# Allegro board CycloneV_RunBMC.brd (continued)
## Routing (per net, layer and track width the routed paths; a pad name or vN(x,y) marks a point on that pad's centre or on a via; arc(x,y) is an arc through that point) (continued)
P0V75_AUX: length 11.7
  BOTTOM w0.254: RB17.2 34,49.13 v1(33.85,49.28) ; v1(46.3,39.63) 46.3,40.39 R8F1.2 ; EU8F1.3 48.19,42.34 ; 48.19,42.34 48.14,42.28 47.89,42.28 C8F2.1 ; 48.19,42.34 v1(48.23,42.37) ; 45.33,44.12 45.31,44.1 v1(44.87,44.1) ; 45.33,44.12 v1(45.36,44.15) 45.35,44.16 RB32.2 RB30.2 45.35,45.27 45.62,45.55 45.62,46.27 CB3.1 ; 45.33,44.12 45.33,43.91 45.32,43.9 RB37.2 RB39.2 45.32,42.42 RB40.2 RB41.2 45.32,41.84 RB42.2 C1A6.1 ; RB16.2 34.51,49.05 34.49,49.08 34.49,49.26 v1(34.46,49.28) ; RB15.2 v1(35.02,49.28) ; 33.84,48.57 33.33,48.57 RB19.2
  vias: v1(35.81,49.28) v1(36.54,49.28) v1(37.28,49.28) v1(38.09,49.28) v1(38.86,49.28) v1(39.59,49.28) v1(40.38,49.28) v1(41.12,49.28) v1(41.93,49.28) v1(42.67,49.28) v1(43.43,49.28)
P0V75_AUX_REFOUT: length 11.2
  TOP w0.254: v1(27.97,43.22) 27.97,43.21 U3.M8 ; U3.H1 v1(33.57,39.2) ; U4.M8 v1(37.75,43.16) ; U4.H1 v1(43.35,39.16) ; U2.M8 v1(18.13,43.23) ; UT7.H28 v1(24.38,30.41) ; U2.H1 v1(23.73,39.23) ; UT7.T27 v1(30.78,29.61)
  BOTTOM w0.254: CB32.1 43.47,39.29 v1(43.35,39.16) ; CB19.1 18.12,43.23 v1(18.13,43.23) ; v1(37.75,43.16) 37.74,43.17 CB21.1 ; v1(23.73,39.23) 23.4,39.56 CB24.1 ; CB66.1 24.07,30.1 v1(24.38,30.41) ; v1(33.57,39.2) 33.24,39.54 CB26.1 ; EU8F1.6 47.19,45.83 46.76,46.26 46.58,46.26 46.45,46.39 ; CB20.1 27.97,43.21 v1(27.97,43.22) ; 46.45,46.39 C8F6.1 ; 46.45,46.39 v1(46.45,46.28) ; v1(30.78,29.61) 30.88,29.61 31.25,29.98 CB68.1
P1V1_AUX: length 45
  TOP w0.254: UT7.M12 v1(27.58,16.81) UT7.N12 ; UT7.P11 v1(28.38,16.01) ; v1(26.01,22.42) 26.02,22.41 26.02,22.39 26.38,22.03 UT7.L18 ; UT7.M13 v1(26.78,17.61) ; UT7.P13 v1(28.38,17.61) ; UT7.R12 v1(29.98,16.81) ; UT7.L11 v1(25.98,16.01) ; v2(12.57,17.3) 12.57,17.87 RT66.2 ; UT7.L12 v1(25.98,16.81) ; UT7.P14 v1(28.38,18.41) ; UT7.R9 v1(29.98,14.41) ; UT7.N16 v1(27.58,20.81) ; UT7.T9 v1(30.78,14.41) ; UT7.P15 v1(28.38,20.01) ; UT7.M15 v1(26.78,20.01) ; UT7.P17 28.76,21.21 28.39,21.58 v1(28.38,21.58) ; UT7.U26 31.56,28.79 v1(31.56,28.81) ; UT7.L16 v1(25.98,20.81) UT7.K17 ; UT7.R10 v1(29.98,15.21) ; UT7.L14 v1(25.98,18.41) ; UT7.N14 v1(27.58,18.41) ; UT7.P19 v1(28.38,23.21) ; UT7.M17 27.16,21.21 26.79,21.58 v1(26.78,21.58) ; UT7.M19 27.04,22.67 27.04,22.5 26.85,22.5 v1(26.78,22.43) 26.91,22.43 26.99,22.35 27.04,22.35 27.04,22.15 UT7.M18 ; v1(27.58,22.43) 27.98,22.03 UT7.N18 ; UT7.R14 v1(29.98,18.41) ; UT7.N10 v1(27.58,15.21) UT7.N9 ; UT7.J11 v1(24.38,16.01) ; UT7.K13 v1(25.18,17.61) ; UT7.N11 v1(27.58,16.01) ; UT7.U21 v1(30.75,24.84) ; UT7.T15 v1(30.78,20.01) ; UT7.K15 v1(25.18,20.01) ; UT7.M9 v1(26.78,14.41)
  BOTTOM w0.254: v1(30.75,24.84) 31.21,25.3 CB93.1 ; v1(24.38,16.01) 24.62,15.77 CB168.1 ; v1(29.98,15.21) 29.65,14.88 CB174.1 ; v1(26.01,22.42) 26.02,22.43 26.09,22.43 CB114.1 ; CB153.1 26.98,19.21 26.96,19.23 26.96,19.83 v1(26.78,20.01) ; CB180.1 v1(26.78,14.41) ; v1(30.78,20.01) 30.59,19.82 CB148.1 ; v1(28.38,23.21) 28.43,23.26 CB111.1 ; v1(28.38,21.58) 28.39,21.59 28.62,21.59 CB128.1 ; CB165.1 29.85,16.68 v1(29.98,16.81) ; v1(27.58,18.41) 27.65,18.48 CB151.1 ; v1(28.38,17.61) 28.54,17.44 CB159.1 ; CB113.1 27.02,22.85 27.02,22.67 v1(26.78,22.43) ; CB167.1 25.74,15.77 v1(25.98,16.01) ; CB178.1 29.71,14.14 v1(29.98,14.41) ; CB130.1 25.43,21.35 v1(25.98,20.81) ; v1(29.98,18.41) 29.77,18.2 CB157.1 ; v1(27.58,15.21) 27.39,15.02 CB175.1 ; CB152.1 16.73,18.03 16.99,17.77 16.99,17.64 17,17.63 17,17.55 v1(17.04,17.58) ; CB155.1 24.39,19.27 24.78,19.67 24.84,19.67 v1(25.18,20.01) ; CB150.1 28.29,18.5 v1(28.38,18.41) ; v1(30.78,14.41) 30.8,14.38 CB176.1 ; CB142.1 28.48,19.91 v1(28.38,20.01) ; CB161.1 27.32,17.06 v1(27.58,16.81) ; CB172.1 28.47,15.92 v1(28.38,16.01) ; v1(25.98,16.81) 26.23,17.06 CB162.1 ; v2(12.57,17.3) 12.5,17.37 12.5,17.66 12.73,17.89 12.73,18.06 RB113.1 14.17,18.19 14.86,17.5 15.91,17.5 15.97,17.56 v1(15.97,17.58)
  vias: v1(16.07,21.6) v1(16.5,17.58) v2(15.03,22.15) v2(15,21.62) v2(15.56,21.97)
P1V1_AUX_VCCEGXB: length 7.1
  TOP w0.254: UT7.T5 v1(30.78,11.21) ; UT7.N5 v1(27.58,11.21) ; UT7.R5 v1(29.98,11.21) ; UT7.M5 v1(26.78,11.21)
  BOTTOM w0.254: v1(26.78,11.21) CB194.1 26.78,12.27 CB187.1 ; CB191.1 30.44,11.47 30.7,11.21 v1(30.78,11.21) ; FBB13.2 27.78,11.73 CB193.1 27.77,11.4 v1(27.58,11.21) ; CB198.1 29.66,10.89 v1(29.98,11.21) 29.57,11.61 CB192.1
P1V1_AUX_VCCLGXB: length 4.7
  TOP w0.254: UT7.T4 v1(30.78,10.41) ; UT7.L4 v1(25.98,10.41)
  BOTTOM w0.254: CB211.1 30.64,8.78 30.55,8.87 30.55,9.78 30.71,9.95 CB202.1 30.96,10.23 v1(30.78,10.41) ; CB200.1 26.14,10.24 v1(25.98,10.41) ; CB208.1 26.35,9.24
P1V2_AUX: length 33.4
  TOP w0.254: 55.59,14.57 55.71,14.46 v1(56.36,14.46) ; UT4.H9 v1(55.38,31.52) ; UT4.G7 v1(58.38,30.52) ; UT4.J9 v1(55.38,33.52) ; UT4.F6 v1(59.38,29.52) ; UT4.K8 v1(57.38,34.52) ; UT4.G9 v1(55.38,30.52) ; UT4.H8 v1(57.38,31.52) ; UT4.H10 v1(54.38,31.52) ; UT4.J8 v1(57.38,33.52) ; UT4.K10 v1(54.38,34.52) ; UT4.J7 v1(58.38,33.52)
  L3-SIG w0.254: v1(54.38,31.52) 53.81,30.95 49.53,30.95 47.54,28.96 v1(46.09,28.96)
  BOTTOM w0.254: CB79.1 57.66,33.8 v1(57.38,33.52) ; CB82.1 58.54,33.67 v1(58.38,33.52) ; v1(59.38,29.52) 59.12,29.25 CB117.1 ; RB129.1 54.58,14.11 54.68,14.01 v1(54.68,13.92) ; U7.1 43.9,25.09 43.55,25.43 v1(43.5,25.43) 43.25,25.68 U7.5 43.25,27.73 CB81.1 43.21,28.11 44.06,28.96 v1(46.09,28.96) ; v1(57.38,31.52) 57.61,31.29 CB98.1 ; CB80.1 54.57,34.33 v1(54.38,34.52) ; CB99.1 55.61,31.29 v1(55.38,31.52) ; v1(55.38,30.52) 55.23,30.36 CB109.1 ; CB100.1 53.93,31.26 54.18,31.52 v1(54.38,31.52) ; CB108.1 58.15,30.28 v1(58.38,30.52) ; v1(57.38,34.52) 57.44,34.57 CB71.1 57.37,35.4 57.37,36.48
  vias: v1(54.15,13.9)
P1V2_AUX_PLL: length 7
  TOP w0.254: UT4.M5 v1(59.48,36.42) ; UT4.D4 v1(61.38,27.52) ; UT4.N13 v1(51.39,36.52) ; UT4.D13 v1(51.38,27.52)
  BOTTOM w0.254: FBB1.2 59.42,36.48 v1(59.48,36.42) 60.3,37.24 CB63.1 ; CB62.1 51.89,36.98 51.48,36.98 51.39,36.89 v1(51.39,36.52) ; CB137.1 61.38,27.04 v1(61.38,27.52) ; v1(51.38,27.52) 51.57,27.7 51.83,27.7 CB129.1
P1V5_AUX: length 77.1
  TOP w0.254: U3.K2 v1(32.77,41.61) ; UT7.AD27 v1(37.18,29.61) ; U4.A8 v1(36.95,33.56) ; U2.D2 v1(22.93,36.03) ; UT5.8 7.19,23.18 v2(7.82,23.81) ; UT7.P27 v1(28.38,29.61) ; U2.H9 v1(16.53,39.23) ; U4.H9 v1(36.15,39.16) ; U4.R9 v1(36.15,45.56) ; U2.B2 v1(22.93,35.23) ; v1(22.78,26.38) 22.78,26.41 UT7.G24 ; U4.D9 v1(36.15,35.96) ; U4.C1 v1(43.35,35.16) ; U2.G7 v1(18.13,38.43) ; U2.H2 v1(22.93,39.23) ; UT7.C27 v1(19.58,29.61) ; UT7.H26 v1(23.58,28.81) ; UT7.F27 v1(21.98,29.61) ; U2.D9 v1(16.53,36.03) ; v1(33.15,29.61) 32.78,29.23 UT7.W27 ; v1(20.38,28.03) 20.38,28.01 UT7.C25 ; U4.N1 v1(43.35,43.96) ; U2.N1 v1(23.73,44.03) ; U4.K8 v1(36.95,41.56) ; U4.H2 v1(42.55,39.16) ; U2.F1 v1(23.73,37.63) ; U4.B2 v1(42.55,34.36) ; U4.A1 v1(43.35,33.56) ; U3.H9 v1(26.37,39.2) ; U4.E9 v1(36.15,36.76) ; U3.N9 v1(26.37,44.01) ; U2.N9 v1(16.53,44.03) ; UT7.L26 26,28.79 v1(26,28.81) ; RB23.2 44.67,46.31 44.67,45.85 44.38,45.56 v1(43.35,45.56) U4.R1 ; U3.A1 v1(33.57,33.6) ; U2.C1 v1(23.73,35.23) ; U3.B2 v1(32.78,35.21) ; UT7.H21 v1(23.58,24.81) ; UT7.T21 v1(29.97,24) ; U2.E9 v1(16.53,36.83) ; U2.R1 v1(23.73,45.63) ; U4.C9 v1(36.15,35.16) ; U2.K8 v1(17.33,41.63) ; UT7.U18 31.56,22.39 v1(31.56,22.41) ; U3.A8 v1(27.17,33.6) ; U4.G7 v1(37.75,39.16) ; U2.R9 v1(16.53,45.63) ; U3.F1 v1(33.57,37.6) ; U3.G7 v1(27.97,38.4) ; U3.N1 v1(33.57,44.01) ; U3.R9 v1(26.37,45.61) ; U4.N9 v1(36.15,43.96) ; U4.K2 v1(42.55,41.56) ; U3.D9 26.72,36.35 26.72,36.14 26.51,36.14 v1(26.37,36) ; U2.K2 v1(22.93,41.63) ; U3.D2 v1(32.79,35.98) ; U2.C9 v1(16.53,35.23) ; U3.C1 v1(33.57,35.2) ; U2.A8 v1(18.13,33.63) ; U3.K8 v1(27.17,41.61) ; U4.F1 v1(43.35,37.56) ; v1(26.78,24.81) 26.78,24.81 UT7.M21 ; UT7.T25 v1(29.98,27.21) ; U3.R1 v1(33.57,45.61) ; U4.D2 v1(42.55,35.96) ; U2.A1 v1(23.73,33.63) ; U3.C9 v1(26.37,35.2) ; U3.H2 v1(32.77,39.2) ; U3.E9 v1(26.37,36.8)
  BOTTOM w0.254: v1(33.57,44.01) 33.59,43.99 CB16.1 ; v1(23.58,24.81) 23.33,24.55 CB102.1 ; v1(23.73,45.63) 23.86,45.76 CB4.1 ; CB50.1 26.14,34.97 v1(26.37,35.2) ; CB54.1 43.37,33.58 v1(43.35,33.56) ; v1(23.73,37.63) 23.86,37.76 CB38.1 ; CB42.1 26.33,36.85 v1(26.37,36.8) ; CB15.1 23.75,44.01 v1(23.73,44.03) ; CB47.1 33.69,35.32 v1(33.57,35.2) ; CB45.1 36.13,35.94 v1(36.15,35.96) ; v1(32.77,39.2) 32.35,39.62 CB27.1 ; CB95.1 29.97,24.73 v1(29.97,24) ; v1(26.78,24.81) 26.55,25.03 CB94.1 ; CB48.1 43.47,35.28 v1(43.35,35.16) ; v1(18.13,38.43) 18.11,38.41 CB34.1 ; CB6.1 33.71,45.74 v1(33.57,45.61) ; CB74.1 28.76,29.23 v1(28.38,29.61) ; 49.29,40.82 49.52,40.82 ; 49.29,40.82 C8F1.1 ; 49.29,40.82 49.28,40.84 C8F3.1 ; 49.52,40.82 v1(49.88,41.18) ; 49.52,40.82 49.59,40.82 49.69,40.72 49.75,40.72 v1(49.85,40.62) ; CB31.1 36.66,39.67 v1(36.15,39.16) ; v1(36.15,36.76) 36.1,36.81 CB44.1 ; CB52.1 23.75,33.64 v1(23.73,33.63) ; CB84.1 30.25,27.48 v1(29.98,27.21) ; v1(42.55,39.16) 42.13,39.58 CB28.1 ; CB39.1 33.71,37.74 v1(33.57,37.6) ; v1(27.97,38.4) 27.95,38.38 CB35.1 ; CB43.1 17.09,36.87 16.57,36.87 v1(16.53,36.83) ; v1(43.35,37.56) 43.48,37.7 CB40.1 ; RB50.1 42.35,36.16 v1(42.55,35.96) ; EU8F1.2 48.69,42.6 49.28,42.01 C8F3.1 ; CB5.1 43.74,45.7 43.48,45.7 v1(43.35,45.56) ; CB25.1 22.51,39.65 v1(22.93,39.23) ; C8F3.1 R8F3.1 ; CB77.1 20.32,27.97 v1(20.38,28.03) ; CB12.1 16.36,44.19 v1(16.53,44.03) ; RB57.1 v1(38.83,31.8) ; CB7.1 26.24,45.74 v1(26.37,45.61) ; v1(26.37,44.01) 26.04,44.34 CB10.1 ; CB49.1 16.65,35.35 v1(16.53,35.23) ; CB9.1 36.14,45.57 v1(36.15,45.56) ; CB13.1 35.94,44.17 v1(36.15,43.96) ; CB53.1 33.59,33.62 v1(33.57,33.6) ; CB67.1 19.49,29.7 v1(19.58,29.61) ; v1(26.37,39.2) 26.88,39.71 CB30.1 ; CB46.1 23.85,35.35 v1(23.73,35.23) ; v1(33.15,29.61) 33.22,29.54 33.22,29.15 CB73.1 ; CB29.1 17.03,39.73 v1(16.53,39.23) ; CB37.1 37.19,38.47 37.75,39.03 v1(37.75,39.16) ; v1(16.53,45.63) 16.49,45.59 CB8.1 ; CB11.1 43.66,43.96 v1(43.35,43.96)
  vias: v2(8.2,24.41) v2(8.83,24.41) v2(8.98,23.78) v2(9.62,23.78)
P1V8_AUX: length 26.5
  L10-SIG w0.254: v1(62.38,9.45) 61.92,9.45 61.11,10.27 61.11,11.92 59.34,13.68 v1(59.34,14.49) 61.75,14.49 61.92,14.66 61.92,19.74 62.76,20.59 62.76,22.33 62.27,22.81 v1(57.12,22.81)
  BOTTOM w0.254: C2L34.1 59.75,13.65 R2L54.1 59.11,14.26 v1(59.34,14.49) ; RB157.1 63.02,9.45 v1(62.38,9.45) ; C308.1 v1(57.12,22.81) 57.16,22.78 57.38,22.78 57.41,22.74 R413.1
  vias: v1(62.38,8.95)
P1V8_P3V3_GPPA_AUX: length 8
  TOP w0.254: UT2.5 14.88,31.88 v1(14.17,32.59) ; UT7.W9 v1(33.18,14.41) ; UT2.1 v1(13.93,30) ; UT2.6 13.93,30.6 v1(14.01,30.51) ; UT2.2 v1(14.88,28.05) ; UT7.AA5 v1(34.78,11.21)
  BOTTOM w0.127: CB179.1 31.87,14.94 32.02,14.79 32.61,14.79 32.99,14.41 v1(33.18,14.41)
  BOTTOM w0.254: CB188.1 34.16,11.83 v1(34.78,11.21)
  vias: v1(1.52,30.49) v1(1.95,30.82) v1(1.97,30.23) v1(2,29.7) v1(10.67,6.48) v1(10.69,6) v1(10.69,5.47) v1(11.08,5.1)
P1V8_P3V3_GPPA_AUX_EDGE: length 86.4
  TOP w0.254: UT2.4 15.83,30.69 16.03,30.49 v1(16.17,30.49)
  L8-SIG w0.254: v1(16.17,30.49) 15.89,30.21 15.89,27.31 15.51,26.93 12.66,26.93 12.41,26.68 12.41,26.32 11.35,25.26 8.65,25.26 8.2,25.71 7.1,25.71 6.27,24.87 6.27,24.16 5.15,23.04 5.15,16.03 3.47,14.36 3.47,5.57 1.62,3.71 1.62,2.27 2.76,1.12 36.14,1.12 37.1,2.09 37.1,3.91 37.83,4.63 39.08,4.64 39.08,4.63 40.15,3.56 40.15,3.17 40.63,2.69 41.24,2.69 41.38,2.82 v1(41.38,3.26)
  BOTTOM w0.254: v1(41.38,3.26) 41.38,3.24 41.37,3.23 41.37,2.93 41.18,2.74 JT3.152
P1V8_USBPHY_AUX: length 6.3
  TOP w0.254: U8A6.30 56.49,13.23 56.37,13.35 56.37,13.53 v1(56.36,13.54) ; U8A6.28 57.49,13.37 v1(57.37,13.49)
  BOTTOM w0.254: v1(57.37,13.49) 56.86,12.98 C2L24.1 C2L31.1 56.23,13.42 v1(56.36,13.54) ; v1(57.37,13.49) 57.56,13.49 57.61,13.54 58.12,13.54 R2L54.2 ; v1(57.37,13.49) 57.88,12.98 C2L25.1 C2L26.1
P1V8_USBPHY_USB2B_AUX: length 6.6
  TOP w0.104: 60.44,20.78 EU12.28 60.45,20.46 v1(60.45,21.18) ; EU12.30 v1(59.44,21.12)
  BOTTOM w0.254: C313.1 59.44,22.03 v1(59.44,21.12) ; C313.1 C314.1 C315.1 60.47,22.04 60.47,21.21 v1(60.45,21.18) ; C313.1 C312.1 58.77,22.12 58.5,21.85 R413.2
P2V5_3V3_VCCPD3A: length 9.7
  TOP w0.127: UT7.AA10 v1(34.78,15.21)
  BOTTOM w0.089: RB126.1 35.49,15.92 v1(34.78,15.21) 34.36,15.63 32.81,15.63 32.07,16.36 31.53,16.36 31.23,16.66 31.23,18.55 31.48,18.8 32.58,18.8 32.75,18.97 RB108.1
P2V5_AUX: length 13.7
  TOP w0.254: UT4.E12 v1(52.38,28.52) ; UT7.M24 v1(26.78,27.21) ; UT7.P21 v1(28.38,24.81) ; UT8.8 v2(7.19,17.54) ; v1(25.16,27.21) 25.18,27.21 UT7.K24 ; UT7.P24 v1(28.38,27.21) ; UT4.M12 v1(53.38,36.52) ; v1(25.16,23.98) 25.16,23.99 UT7.K21 ; UT4.L5 v1(60.38,35.52) ; UT4.D5 v1(60.38,27.52)
  L5-SIG w0.254: 62.71,24.03 v1(62.71,23.99)
  BOTTOM w0.254: CB87.1 28.35,27.18 v1(28.38,27.21) ; CB101.1 28.51,24.94 v1(28.38,24.81) ; v1(60.38,27.52) 60.18,27.32 CB133.1 ; CB118.1 52.18,28.72 v1(52.38,28.52) ; FBB3.1 25.49,26.54 25.49,26.88 v1(25.16,27.21) ; v1(53.38,36.52) 53.41,36.49 CB65.1 ; FBB8.1 62.45,24.58 ; 62.45,24.58 62.45,24.44 62.25,24.24 v1(62.25,24.14) ; 62.45,24.58 62.71,24.33 v1(62.71,23.99) ; CB104.1 25.48,24.25 25.22,23.98 v1(25.16,23.98) ; v1(60.38,35.52) 60.66,35.8 CB69.1
  vias: v2(7.84,18.32) v2(8.48,18.32) v2(9.11,18.32) v2(9.75,18.32)
P2V5_AUX_ADCVREF: length 5.8
  TOP w0.254: UT4.E4 v1(61.38,28.52)
  BOTTOM w0.254: v1(61.38,28.52) 61.63,28.76 CB116.1 61.63,29.1 61.66,29.14 61.66,29.28 62.3,29.92 63.94,29.92 FBB4.2 64.17,29.56 64.17,28.96 64.09,28.89 CB124.1
P2V5_AUX_FILT: length 19.8
  TOP w0.254: UT7.D7 v1(20.38,12.81) ; v1(35.32,24.8) 35.4,24.72 35.67,24.72 UT7.AC21 ; UT7.K5 v1(25.18,11.21) ; UT7.R4 v1(29.98,10.41) ; UT7.P4 v1(28.38,10.41) ; UT7.W5 v1(33.18,11.21) ; v1(24.47,25.57) 24.03,26.01 UT7.H23 ; UT7.AD15 v1(37.18,20.01) ; UT7.M4 v1(26.78,10.41) ; UT7.AA21 v1(34.78,24.81) ; UT7.U4 v1(31.58,10.41) ; UT7.J4 v1(24.38,10.41) ; v1(36.38,13.59) 36.38,13.61 UT7.AC8 ; UT7.F8 v1(21.98,13.61) ; UT7.F21 v1(21.98,24.81) ; UT7.E15 v1(21.18,20.01)
  L6-VCC w0.508: v1(34.78,24.81) 35.31,24.81 v1(35.32,24.8)
  BOTTOM w0.254: v1(24.47,25.57) 24.69,25.57 FBB3.2 ; CB203.1 27.1,10.09 v1(26.78,10.41) ; v1(24.38,10.41) 24.35,10.38 CB205.1 ; v1(21.18,20.01) 21.11,19.94 CB149.1 ; CB189.1 33.24,11.27 v1(33.18,11.21) ; CB107.1 21.94,24.77 v1(21.98,24.81) ; v1(35.32,24.8) 35.95,24.17 CB105.1 ; CB195.1 25.18,11.66 v1(25.18,11.21) ; CB92.1 34.25,25.34 v1(34.78,24.81) ; v1(20.38,12.81) 20.41,12.85 CB181.1 ; CB177.1 35.64,13.96 36,13.61 36.36,13.61 v1(36.38,13.59) ; v1(21.98,13.61) 22.23,13.35 CB183.1 ; CB135.1 37.28,20.11 v1(37.18,20.01)
P2V5_AUX_VCCADC: length 5.3
  TOP w0.254: UT4.E5 v1(60.38,29.52)
  L5-SIG w0.254: v1(63.72,24.08) v1(63.72,23.61)
  BOTTOM w0.254: v1(65.35,30.33) 65.35,29.77 FBB4.1 ; CB122.1 60.8,29.1 v1(60.38,29.52) 59.96,29.1 CB121.1 ; v1(67.4,29.04) 67.3,29.04 67.06,28.8 CB160.1 ; FBB8.2 v1(63.72,24.08)
P3V3_AUX: length 202.7
  TOP w0.254: R4L128.1 v1(1.75,33.68) ; v1(46.07,29.55) RT49.2 RT47.2 ; RT101.1 9,9.44 8.76,9.68 v1(8.43,9.68) ; RT61.1 3.4,18.57 v2(2.89,18.06) ; RT23.2 41.55,31.27 41.45,31.37 v1(41.45,31.83) ; v1(16.26,9.97) 16.2,9.97 16.1,9.87 EUT3.21 ; UT10.8 43.94,9.45 44.04,9.35 44.04,9.23 44.29,8.97 44.39,8.97 v1(44.47,8.9) ; v1(5.99,35.47) 6.01,35.45 RT99.2 ; J4.1 v1(14.16,49.29) ; RT122.1 9.87,6.32 v1(9.9,6.29) ; v1(13.06,37.5) 13.61,36.95 RB25.2 ; J8.4 51.53,49.05 v1(51.73,49.26) ; RT112.1 CT28.1 21.84,7.19 v1(21.91,7.27) ; v1(44.47,12.15) 44.86,12.15 RT97.2 ; v1(41.67,6.96) 41.67,6.96 41.65,6.96 41.58,6.89 41.47,6.89 41.43,6.85 RT108.1 ; RT4.1 11.29,40.66 v1(11.06,40.66) 10.73,40.66 RT3.1 ; RT136.2 RT135.2 35.15,6.33 35.2,6.38 v1(35.2,6.94) ; RB34.2 RT43.2 11.75,28.24 v1(11.98,28.47) ; CT9.1 10.7,31.97 10.98,31.69 v1(10.98,31.47) ; v1(42.28,17.66) 42.18,17.56 RT70.2 ; RT53.1 12.22,24.48 v2(12.13,24.57) ; RT59.2 RT57.2 41.92,20.25 41.92,20.61 41.98,20.67 41.98,20.78 v1(42.03,20.83) ; DST1.1 67.53,38.89 DST2.A v1(68.46,39.02) ; RT46.2 7.98,26.13 v1(7.41,26.7) RT36.2 ; CT6.1 8.54,36.92 v1(7.98,37.47) ; R4L38.1 5.15,33.41 v1(4.67,32.92) ; RT131.1 43.08,5.4 43.4,5.72 43.4,6.1 v1(43.72,6.42) 43.72,6.99 RT105.1 ; v1(14.01,40.44) 14.29,40.44 14.54,40.7 RT5.1 ; v1(9.8,12.1) RT96.1 RT94.1 ; R7A4.1 9.11,40.48 9.25,40.62 v1(9.57,40.62) ; UT3.4 4.86,25.5 4.57,25.2 v1(4.57,24.75) 4.57,24.72 4.1,24.25 RT52.1 ; RT114.2 32.58,6.97 32.33,7.22 v1(31.9,7.22) ; RT106.1 7.11,7.56 7.64,7.56 RT107.1 7.83,7.37 8.27,7.37 v1(8.4,7.24) ; RT24.1 42.61,30.33 42.36,30.08 42.36,29.34 v1(42.24,29.23) 42.09,29.08 RT33.2 RT35.2 42.09,27.96 42,27.87 41.97,27.87 41.6,27.5 v1(41.6,27.46) ; v1(46.17,21.54) 46.26,21.46 RT58.1 ; EUT2.15 2.77,10.12 v1(2.71,10.06) ; v1(16.66,26.32) RT45.1 ; U8A6.21 60.35,10.57 v1(60.39,10.53) ; v1(44.04,15.93) RT89.2 ; v1(11.98,35.47) 11.73,35.22 RT11.2 ; RT109.1 45.59,6.97 45.84,6.71 v1(45.84,6.18) ; R393.1 9.4,10.56 RT100.1 9.11,11.02 v1(9.05,11.08) ; RT98.2 7.79,32.59 v1(7.97,32.42) 7.6,32.42 CT8.1 7.49,31.51 RT21.2 ; v1(3.91,31.15) 3.56,31.15 3.18,30.77 UT1.5 ; R4L40.1 4.97,28.28 v1(5.25,28) ; CT4.1 12.27,37.19 v1(11.98,37.47) ; RT90.2 RT88.2 42.46,15.52 42.72,15.78 v1(42.72,16.28) 42.38,16.62 RT72.2 RT86.2 ; EUT1.21 v1(13.31,12.04) ; v1(14.83,18.55) 14.83,18.61 14.57,18.87 RT63.1 ; R7A54.1 61.58,11.03 v1(62.17,11.03) ; RT93.2 41.01,13.05 41.01,12.88 v1(40.94,12.81) ; EU12.21 63.24,18.31 63.26,18.29 63.31,18.29 v1(63.32,18.29) ; v1(45.15,15.7) 45.18,15.67 RT92.2
  L5-SIG w0.254: v2(12.13,24.57) 16.78,24.57 17.52,23.83 v1(17.62,23.83)
  L6-VCC w0.381: 53.33,12.5 53.36,12.53 v1(53.36,13.47)
  L8-SIG w0.254: v1(12.98,31.47) 12.55,31.91 11.42,31.91 v1(10.98,31.47) ; v1(13.06,37.5) 13.52,37.5 14.01,38 v1(14.01,40.44)
  L10-SIG w0.254: v1(10.98,31.47) 11.42,31.04 11.42,29.04 v1(11.98,28.47)
  BOTTOM w0.089: RT137.2 38.27,25.79 38.47,25.99 39.74,25.99 40,26.24 40,26.99 RB72.1
  BOTTOM w0.254: v1(41.45,31.83) 40.9,31.27 35.8,31.27 35.01,32.06 R432.1 R433.1 ; RB166.1 8.55,7.4 v1(8.4,7.24) ; 62.27,19.31 62.31,19.27 62.31,19.1 ; 62.27,19.31 R396.1 ; 62.27,19.31 62.27,19.14 62.31,19.1 ; RB72.1 40.83,27.03 40.84,27.02 41.22,27.02 41.49,27.29 41.49,27.3 41.6,27.41 v1(41.6,27.46) ; RB33.1 53.64,38.04 54.11,37.57 v1(54.32,37.57) ; UB4.P3 v1(11.98,28.47) ; 65.53,5.89 65.5,5.86 RB189.2 ; 65.53,5.89 65.53,6.3 v1(65.47,6.36) ; 65.53,5.89 RB188.2 ; v1(16.66,26.32) 16.76,26.22 16.76,25.87 16.95,25.68 RB78.1 16.95,24.85 16.91,24.81 16.91,24.45 17.21,24.15 17.3,24.15 v1(17.62,23.83) 17.62,23.63 RB88.2 18.33,23.48 RB95.2 ; RB153.1 v1(8.43,9.68) 8.34,9.68 7.89,9.24 RB158.1 ; RB153.1 RB147.1 v1(9.05,11.08) ; RB153.1 RB160.1 RB164.1 8.98,8.09 7.94,8.09 v1(7.85,8.17) ; v1(63.09,49.18) 63.34,48.93 CRB1.2 ; v1(40.91,9.58) 40.94,9.56 40.94,9.15 RB154.1 ; v1(11.19,6.25) 11.22,6.23 RB82.1 RB73.1 ; FBB10.1 65.88,14.36 v1(67.18,14.36) ; RB87.1 55,28.97 55.24,28.73 RB91.2 RB97.2 ; RB138.2 42.09,11.82 RB139.1 42.27,11.94 42.56,11.94 42.59,11.96 v1(42.61,11.96) ; RB169.1 22.85,7.28 21.93,7.28 v1(21.91,7.27) ; v1(2.71,10.06) 2.71,10.27 3.02,10.57 CB197.1 ; v1(43.24,14.61) 43.24,14.34 43.17,14.28 RB133.2 42.39,14.14 42.22,13.98 RB131.1 RB130.1 ; FB5C1.1 45.38,6.63 v1(45.84,6.18) ; v1(51.43,23.42) 51.56,23.55 RT71.1 ; RB97.2 55.75,28.1 55.59,27.95 55.59,27.46 54.22,26.09 49.81,26.09 v1(49.45,26.45) ; RB97.2 56.34,27.87 56.51,27.7 57.22,27.7 57.47,27.96 RB96.2 ; R8F7.1 48.89,48.65 49.04,48.8 v1(49.04,49.26) ; 62.76,18.66 62.31,19.1 ; 62.76,18.66 62.78,18.63 C310.1 C309.1 62.83,17.81 62.83,17.4 62.58,17.15 C311.1 ; 62.76,18.66 62.76,18.61 62.79,18.58 62.79,18.48 62.88,18.4 63.22,18.4 v1(63.32,18.29) ; U8.5 v1(27.86,5.62) ; v1(14.16,49.29) 14.18,49.27 RB21.1 ; UB5.8 45.22,15.63 v1(45.15,15.7) ; R8F6.1 v1(51.12,49.28) ; UB4.F9 v1(5.01,36.5) ; v1(44.75,23.54) 44.75,23.53 44.82,23.45 44.82,23.37 44.85,23.34 44.85,23.03 R1A9.2 ; v1(54.93,18.15) 55,18.22 55.72,18.22 56.1,17.84 R414.1 ; v1(53.13,45.09) 53.13,45.09 53.13,44.96 53.08,44.91 UB3.5 ; v1(59.97,41.23) 59.97,41.69 60.47,42.19 RB49.1 ; RB46.1 60.47,49.18 v1(60.52,49.23) ; v1(41.67,6.96) 41.65,6.94 41.65,6.76 41.55,6.66 RB178.1 ; v1(7.97,32.42) 7.93,32.42 UB4.L7 ; UB4.H3 v1(11.98,35.47) ; RB105.2 43.55,20.26 RB104.2 43,20.55 43.45,21.01 v1(43.5,21.01) ; v1(6.19,28.36) 6.19,28.68 UB4.P8 ; RB185.1 v1(9.9,6.29) ; v1(42.03,20.83) 42.03,20.77 41.98,20.72 41.98,20.67 41.71,20.4 41.66,20.4 RB102.2 RB106.2 41.59,19.82 RB109.2 ; 33.45,5.87 v1(33.47,5.85) ; v1(33.47,5.85) 33.7,5.62 RB190.2 ; v1(33.47,5.85) 33.47,6.25 33.31,6.42 RB182.1 RB179.1 ; CB204.1 44.35,8.92 44.44,8.92 v1(44.47,8.9) 45.08,8.9 45.18,9 R436.2 45.92,9.76 46.09,9.94 46.09,9.98 46.15,10.03 RB148.2 ; v1(53.36,13.47) 53.43,13.54 53.43,14.19 RB127.1 ; RB116.2 42.08,17.46 v1(42.28,17.66) ; UB1.5 12.94,46.68 13.12,46.86 13.81,46.86 14.17,46.5 v1(14.17,45.83) ; CB186.1 13.69,12.48 13.31,12.1 13.31,12.1 ; UB4.H8 v1(5.99,35.47) ; RB175.1 38.02,6.76 v1(38.17,6.91) ; R3L1.1 9.52,45.19 v1(9.52,45.24) ; R2L48.1 57.61,7.31 57.45,7.14 v1(57.45,7.02) ; UB4.L9 v1(5.01,31.5) ; UB4.L2 v1(12.98,31.47) ; RB142.1 62.88,11.14 62.49,11.14 62.38,11.03 v1(62.17,11.03) 61.96,11.03 C8A32.1 ; v1(54.65,41.51) 54.33,41.83 54.33,42.8 54.55,43.02 CT1.1 55.25,43.13 CT2.1 CB36.1 55.26,44.21 U12.16 ; UB2.5 v1(53.08,49.26) 54.37,49.26 54.65,48.98 CB41.1 ; FBB5.1 13.83,24.43 14.7,24.43 15.03,24.1 RB143.2 ; 13.31,12.1 13.05,12.35 CB185.1 ; 13.31,12.1 v1(13.31,12.04) ; v1(13.06,37.5) 12.54,36.97 UB4.F2 12.48,36.97 v1(11.98,37.47) UB4.F3 11.48,36.97 v1(10.98,37.47) UB4.F4 10.49,36.96 v1(9.99,36.47) UB4.F5 UB4.F6 v1(7.98,37.47) 7.49,36.97 UB4.F7 v1(7.02,36.51) 6.56,36.97 UB4.F8 v1(5.99,37.47) ; U7.6 44.37,26.57 44.42,26.52 v1(44.72,26.52) ; 16.26,10.01 v1(16.26,9.97) 16.1,9.81 15.65,9.81 RB149.1 ; RB24.1 54.88,38.7 55.07,38.51 v1(55.39,38.51) ; v1(60.39,10.53) 60.17,10.53 C8A30.1 C8A31.1 ; UB4.L4 v1(10.98,31.47) ; RB27.1 10.64,46.82 v1(10.51,46.94) 10.76,47.2 R7A1.1 ; FBB9.1 51.19,13.83 51.19,13.2 v1(51.2,13.19) ; RB144.1 v1(10.51,11.21)
  BOTTOM w0.508: v1(2.63,45.26) 3.04,44.86 RB31.1
  vias: v1(2.71,9.51) v2(12.03,23.91)
P3V3_AUX_EDGE: length 12.2
  TOP w0.254: v2(2.15,3.44) 2.43,3.16 JT3.5 ; v2(2.15,3.44) 1.93,3.21 JT3.3 ; v2(2.15,3.44) v2(2.76,3.44) 2.89,3.31 2.89,3.09 2.93,3.05 JT3.7
  BOTTOM w0.254: v2(2.76,3.44) 2.68,3.35 JT3.6 ; RB162.1 v1(2.51,7.9) ; v1(7.13,8.94) 6.6,8.94 RB161.1 ; JT3.4 2.18,3.41 v2(2.15,3.44)
  vias: v1(2.2,8.44) v1(2.81,8.44)
P3V3_AUX_IO: length 96.2
  TOP w0.254: UT7.AG12 v1(39.58,16.81) ; UT7.D18 v1(20.38,22.41) ; UT7.AD9 37.16,14.43 v1(37.18,14.43) ; UT7.E21 v1(21.18,24.81) ; v1(51.39,32.52) 51.39,32.51 UT4.H13 ; v1(40.49,27.47) 40.35,27.61 UT7.AH25 ; UT7.E10 v1(21.18,15.21) ; UT7.E17 v1(21.18,21.61) ; UT4.J4 v1(61.38,33.52) ; UT7.E14 v1(21.18,18.41) UT7.E13 ; UT7.B10 18.82,15.96 v1(18.78,15.96) ; UT7.AG4 38.76,10.39 v1(38.76,10.38) ; UT7.B13 v1(18.78,17.61) ; UT7.W19 v1(33.18,23.21) ; UT7.E7 v1(21.18,12.81) ; UT7.AD21 v1(37.18,24.81) ; UT7.AE21 v1(37.98,24.81) ; UT7.Y21 v1(33.98,24.81) ; v1(57.17,37.5) 57.17,37.31 UT4.N8 ; UT7.F22 v1(21.98,25.61) ; UT7.AA14 v1(34.78,18.41) ; v1(61.53,21.58) 61.53,21.67 61.59,21.72 RT76.1 RT82.1 ; UT4.F13 v1(51.38,29.52) ; UT4.J13 v1(51.38,33.52) ; UT4.D10 v1(54.38,27.52) ; UT7.AC25 v1(36.38,28.01) ; UT4.C7 v1(58.38,26.52) ; UT7.AE13 v1(37.98,17.61) ; UT3.2 v1(1.8,26.45) ; UT7.H10 v1(23.58,15.21) ; UT7.AD13 v1(37.18,17.61) ; UT7.Y10 v1(33.98,15.21) ; v1(57.37,27.26) 57.35,27.28 57.35,27.55 UT4.D8 ; UT4.N11 v1(53.38,37.52) ; UT7.W13 v1(33.18,17.61) ; UT4.M13 v1(52.31,35.59) ; UT4.L13 v1(51.38,35.52) ; UT4.D11 v1(53.38,27.52) ; UT7.AA16 v1(34.78,20.81) ; v1(57.68,37.5) 57.88,37.29 UT4.N7 ; RT79.1 56.69,22.17 RT87.1 56.22,22.27 v1(56.08,22.13) ; v1(51.38,30.46) 51.4,30.49 51.4,30.54 UT4.G13 ; v1(33.15,27.21) 33.15,27.23 UT7.W25 ; UT3.1 v1(1.75,27.4) ; UT4.L4 v1(61.38,34.52) UT4.K4 ; UT4.N10 v1(55.29,36.61) ; RT73.1 v1(64.33,22.14) RT84.1 ; UT3.6 6.23,27.4 v1(6.28,27.45) ; UT7.AD16 36.33,19.96 v1(36.33,19.96) ; UT7.AH15 v1(40.38,20.01) ; UT7.AD24 v1(37.18,27.21) ; UT4.K13 v1(51.38,34.52) ; v1(37.97,18.41) 37.98,18.41 UT7.AF14 ; RB79.1 15.38,18.4 v1(15,18.02) ; UT7.AF19 v1(38.78,23.21) ; UT7.AE10 v1(37.98,15.21) ; UT7.AG22 v1(39.58,25.61) ; v1(6.52,26.29) 6.37,26.45 UT3.5 ; UT7.AD18 v1(37.18,22.41) ; UT7.G5 v1(22.78,11.21) ; UT7.W17 v1(33.18,21.61) ; UT7.J19 v1(24.38,23.21) ; UT4.N6 58.59,37.31 v1(58.59,37.5) ; UT7.C20 v1(19.58,24.01) ; UT7.D6 v1(20.38,12.01) ; UT7.AA12 v1(34.78,16.81) ; UT4.D7 v1(58.38,27.52) ; UT7.H14 v1(23.58,18.41)
  L3-SIG w0.254: v1(64.33,22.14) 64.29,22.18 62.13,22.18 v1(61.53,21.58) ; v1(46.15,35.84) 46.98,35.01 48.3,35.01 49.24,34.07 50.67,34.07 51.12,34.52 v1(51.38,34.52) v1(51.38,33.52) 51.38,32.98 51.39,32.97 v1(51.39,32.52) ; v1(56.08,22.13) 56.13,22.08
  L10-SIG w0.254: v1(56.08,22.13) 60.99,22.13 v1(61.53,21.58)
  BOTTOM w0.089: v1(33.18,21.61) 33.57,22 34.25,22 34.42,22.17 CB106.1
  BOTTOM w0.114: v1(18.78,15.96) 18.56,16.19 CB170.1
  BOTTOM w0.254: CB89.1 v1(51.39,32.52) ; CB134.1 36.24,20.05 v1(36.33,19.96) ; RB71.2 51.42,34.56 v1(51.38,34.52) v1(51.38,35.52) 51.73,35.87 CB70.1 52.03,35.87 v1(52.31,35.59) ; CB85.1 51.36,33.5 v1(51.38,33.52) 51.4,33.54 CB75.1 ; CB61.1 53.24,37.38 v1(53.38,37.52) ; CB196.1 22.78,11.21 v1(22.78,11.21) ; 57.15,37.62 57.17,37.6 v1(57.17,37.5) ; 57.15,37.62 56.74,37.62 56.48,37.88 CB59.1 ; 57.15,37.62 57.13,37.64 57.13,38 CB58.1 CB57.1 57.75,37.99 57.75,37.57 v1(57.68,37.5) ; v1(46.15,35.84) 46.25,35.74 RT28.2 RT34.2 ; v1(51.38,29.52) 51.12,29.25 CB119.1 ; v1(58.38,27.52) 58.08,27.22 CB139.1 ; v1(20.38,12.01) 20.47,11.92 CB190.1 ; v1(21.18,18.41) 21.55,18.04 CB158.1 ; FBB2.1 60.76,33.69 60.92,33.52 v1(61.38,33.52) 61.47,33.61 CB83.1 CB78.1 61.83,34.07 v1(61.38,34.52) 61.69,34.83 CB72.1 ; v1(57.37,27.26) 57.35,27.26 57.31,27.22 CB140.1 ; v1(37.18,22.41) 37.18,22.24 36.92,21.99 CB123.1 ; CB76.1 36.2,27.83 v1(36.38,28.01) ; CB132.1 34.92,20.67 v1(34.78,20.81) ; CB110.1 50.5,29.95 50.83,30.28 51.2,30.28 v1(51.38,30.46) ; v1(34.78,18.41) 34.83,18.46 CB154.1 ; CB156.1 37.11,17.67 v1(37.18,17.61) ; v1(21.98,25.61) 22.29,25.29 CB90.1 ; v1(21.18,21.61) 21.18,21.49 21.75,20.92 RB99.1 ; v1(54.38,27.52) 54.16,27.3 CB136.1 ; 37.16,14.43 v1(37.18,14.43) ; 18.78,15.96 v1(18.78,15.96) ; CB64.1 54.93,36.97 v1(55.29,36.61) 55.32,36.58 CB60.1 ; RB75.2 37.14,27.17 v1(37.18,27.21) ; CB141.1 53.08,27.22 v1(53.38,27.52) ; v1(58.59,37.5) 59.21,38.12 CB56.1 ; CB138.1 58.55,26.69 v1(58.38,26.52) ; v1(34.78,16.81) RB126.2
P3V3_AUX_M10_VCCIO1A: length 3.9
  TOP w0.254: UT4.H4 v1(61.36,32.49) ; UT4.G4 v1(61.37,31.51)
  BOTTOM w0.254: 61.86,31.93 61.86,32 v1(61.36,32.49) 61.36,32.44 61.83,31.97 61.83,32.06 61.78,32.11 ; CB97.1 61.83,31.02 61.37,31.47 v1(61.37,31.51) ; 61.78,32.77 61.78,32.67
P3V3_AUX_SPI: length 24.9
  TOP w0.254: TP1.1 68.57,35.87 v1(68.57,36.28)
  L5-SIG w0.254: v1(68.57,36.28) 68.57,36.76 67.94,37.39 67.94,44.96 65.63,47.27 v1(65.63,49.21)
  BOTTOM w0.254: v1(68.57,36.28) 68.12,36.28 68.09,36.3 RB18.1 66.82,36.81 66.57,37.06 RB38.1 RB29.1 ; EUB1.8 66.54,46.56 CB18.1 ; RB35.1 66.52,47.12 CB18.1 ; v1(65.63,49.21) CRB1.1 66.31,48.29 CB14.1 66.54,47.81 CB18.1
P3V3_SI5338_AUX: length 12.4
  TOP w0.254: EU5C1.20 50.91,10.61 50.77,10.75 v1(50.77,10.91) ; EU5C1.11 47.99,7.18 47.64,6.84 v1(47.64,6.53) ; v1(51.68,9.28) 51.58,9.38 51.52,9.38 51.47,9.43 EU5C1.18 ; v1(49.85,6.66) 49.83,6.69 49.83,6.81 49.58,7.05 49.58,7.06 49.49,7.15 EU5C1.14 ; EU5C1.10 46.49,8.43 46.37,8.31 v1(46.33,8.31)
  BOTTOM w0.254: C5N17.1 51.66,9.3 v1(51.68,9.28) ; FB5C1.2 45.88,7.9 46.07,7.71 C5C7.1 ; v1(50.77,7.78) 50.83,7.84 50.83,8.29 CB209.1 ; C5C2.1 46.81,7.66 46.2,7.66 C5C7.1 ; C5C7.1 46.15,8.12 v1(46.33,8.31) 46.56,8.54 C5C1.1 46.82,9.1 CB201.1 ; v1(49.85,6.66) 49.83,6.69 49.83,6.82 49.52,7.13 C5C13.1 ; CB212.1 48.53,7.13 C5C8.1 47.85,6.74 v1(47.64,6.53) ; v1(50.77,10.91) 50.77,10.88 50.96,10.69 CB199.1
P3V3_USBPHY_AUX: length 7.4
  TOP w0.254: v1(58.52,7.17) 58.44,7.24 58.27,7.24 58.11,7.4 58.11,7.4 58,7.52 U8A6.14 ; R8A64.1 56.97,14.27 57.35,14.65 v1(57.35,14.81) ; U8A6.8 54.63,8.57 54.29,8.22 v1(54.29,8.04) ; v1(54.96,12.98) 55.24,12.98 55.49,12.73 U8A6.32 ; U8A6.11 56.46,7.89 56.46,7.45 56.33,7.32 v1(56.33,7.14)
  BOTTOM w0.254: v1(58.52,7.17) 58.52,7.76 R2L48.2 ; v1(54.96,12.98) 54.96,12.29 54.9,12.22 C2L17.1 ; C2L16.1 56.44,7.6 56.44,7.4 56.43,7.38 56.43,7.29 56.33,7.19 v1(56.33,7.14) ; C2L18.1 54.69,8.45 v1(54.29,8.04)
P3V3_USBPHY_OUT_AUX: length 2.3
  TOP w0.254: v1(60.42,9.94) 60.29,10.07 U8A6.20
  BOTTOM w0.254: v1(60.42,9.94) 60.09,9.61 C7A14.1 C7A15.1
P3V3_USBPHY_USB2B_AUX: length 7.6
  TOP w0.104: 59.56,14.99 59.56,15.02 59.44,15.13
  TOP w0.254: v1(59.57,14.98) 59.44,15.1 EU12.11 ; EU12.14 60.94,15.11 v1(61,15.04) ; EU12.32 58.44,20.6 58.19,20.86 v1(57.96,20.86) ; EU12.8 57.53,16.31 v1(57.24,16.03)
  BOTTOM w0.254: v1(61,15.04) 61.18,15.22 C316.1 ; v1(57.96,20.86) 58.11,20.71 C317.1 58.61,20.71 59.16,20.15 R410.1 ; R414.2 C318.1 56.86,16.41 v1(57.24,16.03)
P3V3_USBPHY_USB2B_OUT_AUX: length 2.6
  TOP w0.104: EU12.20 63.18,17.82 63.24,17.76 v1(63.29,17.76)
  BOTTOM w0.112: v1(63.29,17.76) 64.32,17.76 C319.1 C320.1
P5V_AUX: length 60.8
  TOP w0.254: R392.1 55.08,6.11 v1(55.01,6.19)
  L8-SIG w0.254: v1(65.75,8.77) 65.75,8.63 64.97,7.84 64.97,5.14 65.2,4.91 65.2,2.11 64.2,1.12 44.45,1.12 43.49,2.07 43.49,3.39 43.62,3.52 43.62,4.69 42.61,5.7 37.61,5.7 36.9,4.98 35.42,4.98 35.1,4.67 35.1,4.6 v1(35.07,4.58)
  L10-SIG w0.254: v1(55.01,6.19) 55.01,7.37 55.92,8.29 61.16,8.29 61.51,7.93 62.68,7.93 63.01,8.26 65.38,8.26 65.75,8.63 v1(65.75,8.77)
  BOTTOM w0.254: v1(65.75,8.77) 65.75,8.63 65.02,7.89 62.97,7.89 FB11.1 ; v1(35.07,4.58) 35.09,4.6 35.09,6.16 35.26,6.32 R391.2
P5V_AUX_PIN140: length 4.8
  BOTTOM w0.112: R391.1 36.57,4.63 36.57,4.3 36.39,4.12 36.08,4.12 35.91,3.94 35.91,3.86 35.9,3.85 35.9,3.53 35.9,3.53 35.9,3 35.91,2.99 35.91,2.93 36.18,2.66 JT3.140
P5V_AUX_USB2A_VSENSE: length 3.9
  TOP w0.104: JT3.211 55.93,3.11 56.05,3.23 56.05,4.64 R392.2
P5V_USBPHY_AUX: length 1.7
  TOP w0.254: v1(62.03,8.52) 61.67,8.52 61.59,8.6 61.41,8.6 C3L11.1 61.31,8.76 R7A52.1
P5V_USBPHY_USB2B_AUX: length 5.1
  TOP w0.254: v1(66.77,17.27) 66.77,17.1 67.01,16.86 C322.1 67.01,16.21 C321.1 66.71,16.41 FB17.2
  BOTTOM w0.254: R395.1 64.81,18.75 C305.1 65.47,18.33 66.54,17.27 v1(66.77,17.27)
P5V_USBPHY_USB2B_VSENSE: length 23.8
  TOP w0.254: v1(55.66,3.38) 55.43,3.15 JT3.209 ; FB17.1 65.07,16.08 v1(65.07,15.68)
  L8-SIG w0.254: v1(55.66,3.38) 55.66,2.96 55.95,2.67 60.17,2.67 60.47,2.98 60.47,5.16 61.05,5.75 62.62,5.75 62.88,6.01 62.88,13.26 65.07,15.45 v1(65.07,15.68)
P12V_AUX: length 4.3
  TOP w0.254: v1(6.19,7.17) 6.19,7.14 6.42,6.91 6.42,6.36 6.19,6.13 5.91,6.41 5.91,6.66 5.73,6.84 5.73,7.09 v1(5.66,7.17)
  BOTTOM w0.254: RB171.1 5.7,5.87 5.86,5.87 6.06,6.07 6.06,6.71 5.71,7.07 5.71,7.12 v1(5.66,7.17)
  vias: v1(2.33,11.99) v1(2.36,12.53) v1(2.79,12.76) v1(2.79,12.25) v2(8.15,19.21) v2(8.73,19.82) v2(8.91,19.21)
P12V_AUX_EDGE: length 0.6
  TOP w0.254: 3.14,4.86 3.45,5.16 RT134.1
PVCCIO_CPU0: length 7.7
  TOP w0.104: RT113.1 30.21,5.99 29.38,5.16 29.37,5.16 29.33,5.12 v1(28.95,5.12)
  BOTTOM w0.112: v1(28.95,5.12) 28.59,5.47 28.59,5.49 28.59,5.49 28.59,6.63 28.44,6.79 U8.2 25.18,6.79 CB213.1
PVCCIO_CPU0_CONN: length 6.3
  TOP w0.104: RT113.2 31.54,6.38 30.55,5.39 30.01,5.39 28.9,4.28 28.9,2.95 28.93,2.92 JT3.111
A_BMC_ADC4: length 58.3
  TOP w0.104: UT4.G2 63.16,31.02 v1(63.39,31.26) 63.61,31.48 64.41,31.48 64.56,31.63 64.99,31.63 65.73,30.89 CT11.1
  L8-SIG w0.076: v1(63.39,31.26) 63.39,30.69 64.38,29.7 65.78,29.7 66.38,29.1 66.38,23.61 65.46,22.69 65.46,17.11 66.3,16.27 66.3,14.9 64.62,13.23 64.62,4.95 64.03,4.35 64.03,2.24 63.24,1.45 49.43,1.45 47.92,2.96 47.92,3.85 48.4,4.32 v1(48.79,4.32)
  BOTTOM w0.112: v1(48.79,4.32) 48.79,4.15 48.72,4.07 48.72,2.92 48.68,2.88 JT3.182
A_EMMC_VDDIM_DECAP: length 3.1
  TOP w0.104: CT5.1 9.51,37 v1(10,37.49) 9.62,37.88 8.74,37.88 CT3.1
  BOTTOM w0.127: UB4.E4 v1(10,37.49)
A_P1V05_PCH_AUX_SENSE: length 49.9
  TOP w0.127: UT4.G5 v1(59.38,31.52)
  L5-SIG w0.076: v1(59.38,31.52) 59.82,31.96 61.59,31.96 61.75,31.8 61.75,29.96 59.96,28.17 59.96,23.68 59.1,22.81 58.67,22.81 57.68,21.82 57.68,21.21 57.48,21.02 57.48,19.65 55.44,17.61 55.44,16.21 54.93,15.7 52.24,15.7 50.5,13.96 50.5,13.94 50.03,13.47 50.03,12.25 48.56,10.78 48.56,5.92 47.94,5.3 47.94,3.49 v1(48.31,3.12)
  BOTTOM w0.112: v1(48.31,3.12) 48.18,2.99 JT3.180 ; v1(59.38,31.52) UT4.G5 60.52,31.02 60.78,30.76 60.78,30.26 61,30.03 61.64,30.03 62.02,30.41 63.27,30.41 64.48,31.63 65.27,31.63 65.78,31.12 CB96.1
A_P1V8_PCH_AUX_SENSE: length 48.4
  TOP w0.104: CT16.1 65.73,28.35 v1(65.6,28.22) 65.27,28.56 64.34,28.56 UT4.E1
  L8-SIG w0.076: v1(65.6,28.22) 65.9,27.93 65.9,23.82 64.95,22.88 64.95,16.88 65.82,16.02 65.82,15.21 63.49,12.88 63.49,5.59 63.16,5.26 63.16,3.83 63.37,3.63 63.37,2.6 62.83,2.06 50.74,2.06 50.02,2.78 50.02,3.7 50.18,3.86 v1(50.41,3.86)
  BOTTOM w0.112: JT3.186 49.68,2.75 49.88,2.95 49.88,3.71 50.03,3.86 v1(50.41,3.86)
A_P3V3_SCALED_SENSE: length 42.2
  TOP w0.104: CT12.1 65.89,30.33 65.43,30.79 64.53,30.79 64.38,30.64 61.5,30.64 v1(61.26,30.4) UT4.F4
  L5-SIG w0.076: v1(61.26,30.4) 61.26,29.85 60.57,29.16 59.17,29.16 58.9,28.89 58.9,25.48 58.18,24.77 58.18,22.74 56.38,20.94 55.36,20.94 51.05,16.62 51.05,14.97 49.75,13.67 49.75,12.35 48.25,10.85 48.25,7.73 47.24,6.72 47.24,6.53 47.02,6.3 47.02,5.36 v1(46.97,5.31)
  BOTTOM w0.112: JT3.176 47.18,2.66 47.38,2.86 47.38,4.9 v1(46.97,5.31)
A_P3V_BAT_SENSE: length 44.8
  TOP w0.104: UT4.D1 64.99,28.02 v1(65.47,27.54) 65.63,27.54 65.8,27.72 CT17.1
  L8-SIG w0.076: v1(65.47,27.54) 65.04,27.11 65.04,23.45 63.52,21.93 63.52,20.3 64.13,19.69 64.13,17.33 65.58,15.88 65.58,15.32 63.21,12.96 63.21,5.72 62.92,5.43 62.92,4.21 62.27,3.56 62.27,2.9 61.68,2.3 50.98,2.3 50.41,2.88 v1(50.41,3.33)
  BOTTOM w0.112: JT3.188 50.18,2.97 50.41,3.2 v1(50.41,3.33)
A_P5V_AUX_SCALED_SENSE: length 53.9
  TOP w0.104: UT4.F1 65.04,28.86 v1(65.63,28.86) 65.75,28.99 CT15.1
  L8-SIG w0.076: v1(65.63,28.86) 66.14,28.35 66.14,23.71 65.22,22.79 65.22,16.97 66.06,16.13 66.06,15.02 64.42,13.38 64.42,5.99 63.46,5.03 63.46,4.35 63.7,4.11 63.7,2.32 63.14,1.76 50.51,1.76 49.78,2.49 49.78,4.35 49.38,4.74 49.38,5.14 49.78,5.54 v1(49.85,5.54)
  BOTTOM w0.112: v1(49.85,5.54) 49.62,5.54 49.19,5.11 49.19,4.03 48.95,3.79 48.95,2.99 49.18,2.77 JT3.184
A_P12V_SCALED_SENSE: length 47.1
  TOP w0.254: UT4.F5 59.88,30.02 v1(60.38,30.52)
  L5-SIG w0.076: v1(46.44,5.35) 46.23,5.56 46.23,7.29 46.79,7.85 46.79,10.57 47.57,11.34 47.57,11.97 48.73,13.14 48.73,15.6 49.7,16.57 50.18,16.57 55.21,21.6 56.06,21.6 56.64,22.18 56.64,22.84 57.04,23.25 57.19,23.25 57.58,23.63 57.58,24.31 56.86,25.02 56.86,30.69 57.12,30.94 59.95,30.94 v1(60.38,30.52)
  BOTTOM w0.112: v1(46.44,5.35) 45.92,4.83 45.92,3.47 46.41,2.98 46.41,2.92 46.68,2.65 JT3.174 ; v1(60.38,30.52) 60.38,30.07 60.67,29.77 61.75,29.77 62.18,30.2 63.36,30.2 63.36,30.21 63.67,30.21 64.26,30.79 65.44,30.79 65.82,30.41 CB103.1
A_PVCCIN_CPU0_SCALED: length 32.4
  TOP w0.104: UT4.C4 v1(61.39,26.51) ; v1(65.5,24.34) 65.75,24.59 CT22.1
  L3-SIG w0.076: v1(61.39,26.51) 61.39,26.78 61.61,27.01 64.56,27.01 65.09,26.47 65.09,24.75 v1(65.5,24.34)
  L5-SIG w0.076: v1(67.42,8.62) 66.96,9.09 66.96,10.69 66.08,11.56 66.08,15.92 65.47,16.53 65.47,24.03 65.5,24.06 v1(65.5,24.34)
  BOTTOM w0.112: JT3.252 66.18,2.87 66.47,3.16 66.47,4.27 66.17,4.56 66.17,4.68 66.12,4.73 66.12,6.58 66.17,6.63 66.17,6.64 66.4,6.86 66.4,6.87 67.42,7.9 v1(67.42,8.62)
A_PVCCIN_CPU1_SCALED: length 29.9
  TOP w0.104: CT18.1 65.6,27.08 65.53,27.01 v1(65.5,27.01) 64.28,27.01 64.26,27.02 UT4.C1
  L3-SIG w0.076: v1(68.01,14.2) 67.25,14.97 67.25,15.65 66.36,16.54 66.36,17.48 65.83,18.01 65.83,22.79 66.21,23.17 66.21,25.1 65.53,25.79 65.53,26.61 65.5,26.63 v1(65.5,27.01)
  BOTTOM w0.112: v1(68.01,14.2) 68.01,8.13 66.36,6.48 66.36,4.83 66.68,4.52 66.68,4.4 66.7,4.37 66.7,1.6 JT3.254
A_PVCCIO_CPU0_SENSOR: length 30.4
  TOP w0.104: UT4.B1 64.12,25.78 v1(64.64,25.78) 65.53,25.78 65.65,25.66 CT20.1
  L5-SIG w0.076: v1(68.31,3.05) 68.04,2.78 67.33,2.78 66.74,3.37 66.74,3.97 64.68,6.03 64.68,9.98 65.6,10.9 65.6,15.72 64.14,17.18 64.14,20.93 64.11,20.96 64.11,21.64 63.93,21.83 63.93,23.04 64.18,23.3 64.18,25.31 v1(64.64,25.78)
  BOTTOM w0.112: JT3.260 68.18,2.92 v1(68.31,3.05)
A_PVDDQ_ABC_CPU0_SENSOR: length 35.2
  TOP w0.127: UT4.E3 v1(62.38,28.52)
  L3-SIG w0.076: v1(68.03,14.84) 68.19,15.01 68.19,16.79 67.82,17.16 67.73,17.2 67.46,17.38 67.11,17.72 67.01,17.97 66.14,18.84 66.14,21.53 66.6,21.99 66.6,25.6 66.24,25.96 66.24,28.78 65.78,29.23 64.05,29.23 63.33,28.52 v1(62.38,28.52)
  BOTTOM w0.112: CB120.1 62.54,28.36 v1(62.38,28.52) ; JT3.256 67.18,2.82 67.02,2.98 67.02,3.64 68.85,5.47 68.85,14.01 v1(68.03,14.84)
A_PVDDQ_ABC_CPU1_SENSOR: length 31.8
  TOP w0.104: UT4.C2 63.4,26.5 65.73,26.5 65.78,26.45 CT19.1 66.12,26.2 66.25,26.07 67.26,26.07 v1(67.34,26.14)
  L5-SIG w0.076: v1(67.34,26.14) 66.61,25.42 66.61,18.78 68.67,16.72 68.67,9.68 69.01,9.35 69.01,3.89 68.73,3.61 v1(68.34,3.61)
  BOTTOM w0.112: JT3.258 67.68,2.87 67.91,3.1 67.91,3.41 68.12,3.61 v1(68.34,3.61)
A_PVDDQ_DEF_CPU0_SENSOR: length 36.5
  TOP w0.104: JT3.255 66.93,4.7 66.29,5.34 66.29,6.76 66.62,7.09 v1(66.62,8.05) ; CT13.1 64.92,29.75 64.81,29.85 v1(64.81,30.36) 64.8,30.38 63.24,30.38 UT4.F2
  L5-SIG w0.076: v1(64.81,30.36) 64.81,30.23 66.31,28.73 66.31,23.78 65.83,23.3 65.83,19.2 68.43,16.59 68.43,8.72 67.76,8.05 v1(66.62,8.05)
A_PVDDQ_DEF_CPU1_SENSOR: length 28.7
  TOP w0.104: v1(67.43,3.23) JT3.257
  TOP w0.127: UT4.B2 63.38,25.52 64.14,25.52 64.5,25.16 v1(65.49,25.16) 65.53,25.13 CT21.1
  L5-SIG w0.076: v1(65.49,25.16) 65.07,24.75 65.07,16.59 65.84,15.82 65.84,11.46 66.72,10.59 66.72,9.21 66.21,8.7 66.21,7.91 66.44,7.68 66.44,6.9 66.4,6.7 66.4,5.72 66.44,5.52 66.55,5.35 67.43,4.47 v1(67.43,3.23)
A_PVMCP_CPU0_SENSOR: length 30.3
  TOP w0.104: v1(67.56,13.32) 68.52,12.35 68.52,7.42 68.83,7.12 68.83,4.93 67.93,4.03 JT3.259
  TOP w0.127: UT4.C3 v1(62.38,26.52)
  L3-SIG w0.076: v1(67.56,13.32) 66.74,14.13 66.74,15.86 65.53,17.07 65.53,23.65 64.86,24.31 64.38,24.31 64.15,24.54 64.15,25.51 63.14,26.52 v1(62.38,26.52)
  BOTTOM w0.112: v1(62.38,26.52) 62.76,26.52 62.84,26.45 CB143.1
A_PVNN_PCH_AUX_SENSE: length 46.8
  TOP w0.127: UT4.H5 v1(60.38,31.52)
  L5-SIG w0.076: v1(46.63,5.87) 46.63,6.37 46.47,6.53 46.47,7.19 47.04,7.75 47.04,10.42 47.95,11.33 47.95,11.99 49.36,13.41 49.36,15.72 49.88,16.24 50.26,16.24 55.33,21.3 56.34,21.3 57.96,22.92 57.96,29.77 58.18,30 60.52,30 60.83,30.31 60.83,31.07 v1(60.38,31.52)
  BOTTOM w0.112: CB91.1 66.02,31.96 63.44,31.96 62.81,31.32 62.81,30.84 62.63,30.66 61.59,30.66 61.39,30.87 61.03,30.87 v1(60.38,31.52) ; JT3.178 47.68,2.88 47.75,2.95 47.75,5.09 46.96,5.87 v1(46.63,5.87)
A_USBPHY_PCH_VBUS: length 1.9
  TOP w0.104: U8A6.22 60.39,11.07 61.03,10.43 R7A52.2
A_USBPHY_USB2B_VBUS: length 1.3
  TOP w0.104: EU12.22 63.33,18.82 v1(63.34,18.83)
  BOTTOM w0.112: R395.2 63.85,18.83 v1(63.34,18.83)
CLK_25M_HPS_CLK1: length 63
  TOP w0.104: RT118.2 49.24,5.16 49.45,4.96 v1(49.83,4.96)
  TOP w0.127: UT7.E20 v1(21.18,24.01)
  L5-SIG w0.076: v1(21.18,24.01) 21.61,23.58 21.61,23.55 23.11,22.05 24.99,22.05 25.57,21.47 25.57,8.62 22.35,5.39 22.35,3.1 23.95,1.5 36.47,1.5 37.01,2.05 37.01,4.09 37.78,4.86 38.8,4.86 40.14,3.53 40.14,2.5 41.48,1.15 48.97,1.15 49.88,2.06 49.88,4.91 v1(49.83,4.96)
CLK_25M_HPS_CLK1_R: length 1.1
  TOP w0.104: EU5C1.13 48.99,6.94 49.24,6.69 RT118.1
CLK_25M_HPS_CLK2: length 62.5
  TOP w0.104: RT117.2 47.91,5.59 v1(47.55,5.95)
  TOP w0.127: UT7.D20 v1(20.38,24.01)
  L5-SIG w0.076: v1(47.55,5.95) 47.55,1.83 47.22,1.5 41.75,1.5 40.42,2.84 40.42,3.58 38.84,5.16 37.74,5.16 36.73,4.16 36.73,3.34 36.73,3.34 36.73,2.97 36.73,2.41 36.16,1.83 25.01,1.83 23.11,3.74 23.11,4.25 23.29,4.42 23.29,5.47 26.38,8.57 26.38,22.56 26.13,22.81 23.01,22.81 21.43,24.39 20.76,24.39 v1(20.38,24.01)
CLK_25M_HPS_CLK2_R: length 1.1
  TOP w0.104: RT117.1 48.38,6.53 48.49,6.64 EU5C1.12
CLK_25M_M10: length 30.6
  TOP w0.104: R5N6.2 44.91,9.86 44.59,9.86 v1(44.49,9.96)
  TOP w0.127: UT4.J11 v1(53.41,32.55)
  L5-SIG w0.076: v1(44.49,9.96) 43.94,10.52 43.94,13.04 48.73,17.83 49.52,17.83 50.21,18.52 50.21,21.21 51.01,22.01 51.01,24.12 49.93,25.2 49.93,29.34 50.56,29.98 52.47,29.98 52.88,30.38 52.88,32.01 v1(53.41,32.55)
CLK_25M_M10_R: length 1.2
  TOP w0.104: EU5C1.8 46.51,9.43 46.28,9.66 R5N6.1
CLK_50M_C5_FPGA: length 19.7
  TOP w0.104: v1(44.49,9.43) 44.62,9.3 44.63,9.3 45.01,8.92 RT102.2
  TOP w0.127: v1(32.38,15.16) 32.38,16.01 UT7.V11
  L3-SIG w0.076: v1(32.38,15.16) 32.71,14.84 35.1,14.84 35.48,14.46 35.48,12.63 36.47,11.64 39.16,11.64 39.9,12.38 43.38,12.38 43.88,11.87 43.88,9.66 44.11,9.43 v1(44.49,9.43)
CLK_50M_C5_FPGA_R: length 1.1
  TOP w0.104: RT102.1 46.44,8.92 46.45,8.93 EU5C1.9
CLK_50M_CKMNG_BMCB: length 38.8
  TOP w0.127: UT7.V12 v1(32.38,16.81)
  L3-SIG w0.076: v1(32.38,16.81) 32.38,17.05 32.56,17.23 35.68,17.23 36.49,16.41 41.65,16.41 42.34,15.73 43.02,15.73 43.94,14.81 44.75,14.81 45.66,13.9 49.73,13.9 50.18,14.36 51.81,14.36 52.37,13.8 52.37,13.09 53.36,12.1 53.36,6.66 54.53,5.49 55.14,5.49 56.1,4.53 57.61,4.53 57.62,4.54 v1(57.8,4.54)
  BOTTOM w0.112: v1(57.8,4.54) 58,4.54 58.26,4.28 58.26,3.29 58.18,3.21 JT3.220
CLK_100M_BMC_PE_DN: length 18.8
  TOP w0.104: JT3.159 43,1.64 43,3.23 v1(42.92,3.31)
  TOP w0.127: UT7.V4 v1(32.38,10.41)
  L3-SIG w0.076: v1(32.38,10.41) 32,10.03 32,9.4 32.4,9 32.4,7.65
  L3-SIG w0.091: 32.4,7.65 32.4,6.83 32.86,6.37 33.63,6.37 34.14,5.85 40.98,5.85 42.33,4.5 42.33,3.59 42.61,3.31 v1(42.92,3.31)
CLK_100M_BMC_PE_DP: length 19.4
  TOP w0.104: v1(42.97,3.84) 42.99,3.84 43.02,3.87 43.17,3.87 43.39,3.65 43.39,1.64 43.43,1.6 JT3.161
  TOP w0.127: UT7.V5 v1(32.38,11.21)
  L3-SIG w0.076: 32.83,7.65 32.83,10.76 v1(32.38,11.21)
  L3-SIG w0.091: 32.83,7.65 32.83,7 33.04,6.79 33.8,6.79 34.32,6.27 34.49,6.27 34.49,6.27 41.15,6.27 42.75,4.67 42.75,4 42.88,3.87 42.92,3.87 42.95,3.84 v1(42.97,3.84)
DBG_RSMRST_MONITOR_N: length 88.9
  TOP w0.104: v1(59.45,34.55) 59.41,34.55 UT4.K6 ; JT3.103 26.93,2.84 v1(27.27,3.18)
  L3-SIG w0.076: v1(27.27,3.18) 29.3,1.15 35.91,1.15 37.18,2.42 37.18,3.97 37.87,4.65 38.7,4.65 39.97,3.38 39.97,2.19 41.62,0.55 66.35,0.55 67.81,2.01 67.81,3.71 69.01,4.91 69.01,16.59 68.06,17.53 67.93,17.58 67.73,17.72 67.57,17.88 67.43,18.08 67.38,18.21 66.71,18.89 66.71,21.48 67.03,21.81 67.03,25.92 66.77,26.18 66.77,31.2 64.34,33.63 62.26,33.63 61.84,34.04 59.96,34.04 v1(59.45,34.55)
DBG_XDP_SYSPWROK_HOOK3: length 18.7
  TOP w0.104: JT3.119 30.93,2.88 31.16,3.12 31.16,3.49 30.66,3.98 v1(30.66,4.83)
  TOP w0.127: UT7.W11 v1(33.18,16)
  L5-SIG w0.076: v1(30.66,4.83) 30.66,4.54 30.5,4.37 29.97,4.37 29.74,4.6 29.74,5.99 30.67,6.92 30.67,7.47 31.29,8.08 31.41,8.08 31.95,8.62 31.95,11.44 33.54,13.03 33.54,15.65 v1(33.18,16)
DBP_DEBUG_EN_N: length 29.3
  TOP w0.104: v1(23.53,3.88) 23.53,3.5 23.43,3.4 JT3.89
  TOP w0.127: UT7.AD10 v1(37.18,15.21)
  L8-SIG w0.076: v1(23.53,3.88) 22.83,3.88 22.36,4.35 22.36,5.35 23.83,6.81 25.11,6.81 25.54,7.24 28.7,7.24 29.83,8.37 30.05,8.37 30.34,8.66 30.34,8.88 31.43,9.97 31.65,9.97 31.94,10.26 31.94,10.48 32.23,10.77 32.45,10.77 32.74,11.06 32.74,11.28 34.11,12.65 35.2,12.65 35.93,13.39 35.93,13.96 v1(37.18,15.21)
  BOTTOM w0.089: v1(37.18,15.21) 37.55,14.84 40.05,14.84 40.4,14.49 40.73,14.49
  BOTTOM w0.112: 40.73,14.49 40.97,14.49 41.01,14.53 RB130.2
DBP_JUMPER_EN_DET: length 18
  TOP w0.104: JT3.99 25.93,3.09 26.19,3.35 v1(26.19,3.35)
  TOP w0.127: UT7.T11 v1(30.78,16.01)
  L5-SIG w0.076: v1(30.78,16.01) 30.37,15.6 29.28,15.6 28.9,15.22 28.9,7.65 27.68,6.43 27.09,6.43 26.59,5.93 26.59,3.75 v1(26.19,3.35)
DBP_PRDY_N: length 24
  TOP w0.104: JT3.83 21.93,3.17 21.93,3.17 v1(21.93,3.18)
  TOP w0.127: UT7.AF4 v1(37.96,10.39)
  L8-SIG w0.076: v1(21.93,3.18) 22.2,2.9 23.85,2.9 24.53,3.59 24.87,3.59 25.76,2.7 28.8,2.7 28.92,2.82 28.92,4.42 29.42,4.92 29.42,5.48 30.65,6.71 32.12,6.71 32.53,7.12 32.53,7.65 33.62,8.73 33.62,8.96 33.9,9.25 34.13,9.25 34.42,9.53 34.42,9.76 34.65,9.99 37.56,9.99 v1(37.96,10.39)
DBP_PREQ_N: length 28.2
  TOP w0.104: JT3.85 22.43,4.69 v1(22.75,5.01)
  TOP w0.127: v1(37.98,14.43) 37.96,14.43 UT7.AE9
  L8-SIG w0.076: v1(22.75,5.01) 24.15,6.41 25.27,6.41 25.77,6.91 29.41,6.91 31.03,8.54 31.03,8.77 31.5,9.25 31.73,9.25 32.02,9.53 32.02,9.76 32.3,10.05 32.53,10.05 32.74,10.26 32.74,10.48 33.1,10.85 33.33,10.85 33.54,11.06 33.54,11.28 34.63,12.37 37.25,12.37 37.59,12.7 37.59,14.04 v1(37.98,14.43)
  BOTTOM w0.089: 40.73,14.25 39.91,14.25 39.72,14.06 38.33,14.06 38.24,14.14 38.24,14.16 v1(37.98,14.43)
  BOTTOM w0.112: RB131.2 41.19,13.98 40.92,14.25 40.73,14.25
DBP_PWR_DEBUG_HOOK2_N: length 24.2
  TOP w0.104: RT112.2 22.4,6.13 23.18,5.34 23.18,4.17 22.96,3.95 v1(22.96,3.28) 22.96,3.26 22.93,3.23 JT3.87
  TOP w0.127: UT7.AE4 37.17,10.4 v1(37.17,10.37)
  L8-SIG w0.076: v1(22.96,3.28) 22.98,3.3 23.9,3.3 24.43,3.83 25.26,3.83 25.62,4.2 25.62,5.36 26.43,6.18 29.61,6.18 31.21,7.78 31.54,7.78 32.13,8.37 32.46,8.37 32.82,8.72 32.82,8.96 33.03,9.17 33.26,9.17 33.62,9.52 33.62,9.76 33.83,9.97 34.06,9.97 34.42,10.32 34.42,10.56 34.63,10.77 36.77,10.77 v1(37.17,10.37)
DBP_SMC_NTRST_N: length 16.6
  TOP w0.127: UT7.AE7 v1(37.98,12.81)
  BOTTOM w0.112: v1(37.98,12.81) 38.43,12.36 38.85,12.36 40.12,11.09 41.21,11.09 41.56,11.44 42.31,11.44 42.77,10.98 42.77,10.7 42.61,10.55 42.61,6.2 43.81,5.01 43.81,3.6 43.57,3.36 43.57,3.04 43.73,2.87 43.73,1.63 JT3.162
DBP_SMC_TCK: length 13.2
  L8-SIG w0.076: v1(43.22,11.46) 43.58,11.11 43.58,8.9 45.15,7.32 45.15,6.15 45.57,5.73 45.57,4.69 v1(45.15,4.27)
  BOTTOM w0.112: JT3.170 45.68,2.88 45.43,3.14 45.43,4 v1(45.15,4.27) ; RB134.2 43.22,12.44 v1(43.22,11.46)
DBP_SMC_TCK_R: length 4.5
  TOP w0.127: v1(37.98,13.59) 37.98,13.61 UT7.AE8
  BOTTOM w0.089: 40.73,13.21 38.35,13.21 v1(37.98,13.59)
  BOTTOM w0.112: 40.73,13.21 41.56,13.21 RB134.1
DBP_SMC_TDI: length 16.7
  BOTTOM w0.112: JT3.166 44.68,2.88 44.6,2.97 44.6,3.44 44.3,3.73 44.3,5.24 44.29,5.25 44.29,5.29 44.16,5.42 44.16,6.9 43.18,7.88 43.18,10.26 43.87,10.95 43.87,11.7 43.77,11.8 43.77,12.76 43.99,12.98 43.99,14.82 43.99,14.82 43.99,14.86 43.3,15.55 42.5,15.55 RB125.2
DBP_SMC_TDI_R: length 4.2
  TOP w0.127: UT7.AE11 v1(37.98,16.01)
  BOTTOM w0.089: 40.73,15.23 40.17,15.23 39.77,15.63 38.36,15.63 v1(37.98,16.01)
  BOTTOM w0.112: RB125.1 41.18,15.12 40.85,15.12 40.82,15.14 40.82,15.14 40.73,15.23
DBP_SMC_TDO: length 20.7
  TOP w0.127: UT7.AF9 38.76,14.43 v1(38.78,14.43)
  L10-SIG w0.076: v1(38.78,14.43) 39.09,14.43 39.44,14.09 39.83,14.09 40.23,14.48 41.78,14.48 42.44,15.14 v1(42.94,15.14)
  BOTTOM w0.112: JT3.164 44.18,2.88 44.34,3.04 44.34,3.36 44.06,3.64 44.06,5.14 43.22,5.97 43.22,6.53 43.53,6.84 43.53,7.19 42.94,7.78 42.94,7.79 42.94,7.79 42.94,10.36 43.63,11.05 43.63,11.6 43.53,11.7 43.53,12.86 43.76,13.08 43.76,14.72 43.33,15.14 v1(42.94,15.14)
DBP_SMC_TMS: length 18
  BOTTOM w0.112: RB122.2 42.1,15.9 42.55,15.9 42.56,15.89 43.39,15.89 44.23,15.05 44.23,12.89 44.01,12.66 44.01,11.9 44.11,11.8 44.11,10.85 43.42,10.16 43.42,7.98 44.4,7 44.4,6.99 44.4,6.07 44.54,5.92 45.31,5.92 45.68,5.56 45.68,3.31 46.18,2.81 JT3.172
DBP_SMC_TMS_R: length 4.9
  TOP w0.127: UT7.AD11 v1(37.18,16.01)
  BOTTOM w0.112: RB122.1 40.75,15.93 40.26,16.41 37.58,16.41 v1(37.18,16.01)
DBP_TCK_MUX_SEL: length 22.9
  TOP w0.104: JT3.95 24.93,2.88 25.14,3.1 25.14,3.74 25.03,3.85 v1(25.03,4.23)
  TOP w0.127: UT7.AF8 38.78,13.61 v1(38.78,13.59)
  L8-SIG w0.076: v1(25.03,4.23) 25.35,4.55 25.35,5.73 26.18,6.56 29.56,6.56 31.1,8.1 31.5,8.1 31.94,8.53 31.94,8.88 32.23,9.17 32.45,9.17 32.74,9.46 32.74,9.68 33.03,9.97 33.25,9.97 33.54,10.26 33.54,10.48 33.83,10.77 34.05,10.77 34.34,11.06 34.34,11.28 34.67,11.61 37.81,11.61 38.35,12.15 38.35,13.16 v1(38.78,13.59)
DBP_XDP_PRSNT_N: length 22.3
  TOP w0.104: v1(23.92,4.25) 23.92,2.89 23.93,2.88 JT3.91
  TOP w0.127: UT7.U11 v1(31.58,16.01)
  L5-SIG w0.076: v1(31.58,16.01) 31.31,16.01 30.91,16.41 28.27,16.41 27.96,16.1 27.96,7.65 25.6,5.29 25.6,4.04 25.37,3.82 24.1,3.82 23.92,3.99 v1(23.92,4.25)
EMMC_SMC_CLK: length 81.8
  TOP w0.104: RT138.2 9.35,25.3 9.16,25.49 v1(9.16,26.07) RT46.1 8.45,26.13 RT38.1
  TOP w0.127: UT7.AD26 v1(36.42,28.77)
  L3-SIG w0.076: v1(9.16,26.07) 10.2,26.07 11.55,27.41 13.53,27.41 14.7,28.58 14.7,31 14.62,31.07 14.01,31.07 13.94,31.15 13.94,31.3 14.01,31.38 14.62,31.38 14.7,31.46 14.7,31.61 14.62,31.68 14.01,31.68 13.94,31.76 13.94,31.91 14.01,31.99 14.62,31.99 14.7,32.06 14.7,45.22 16.3,46.82 43.39,46.82 43.76,46.45 43.76,35.82 43.5,35.57 40.28,35.57 37.33,32.62 37.2,32.62 36.62,32.03 36.62,30.94 36.77,30.79 36.77,29.12 v1(36.42,28.77)
EMMC_SMC_CLK_CONN: length 80.7
  TOP w0.104: JT1.10 v1(64.99,49.15) ; v1(11.27,25.89) 11.07,25.68 11.06,25.68 RT138.1
  L8-SIG w0.076: v1(64.99,49.15) 64.23,48.39 49.68,48.39 49.2,47.91 16.22,47.91 15,46.69 14.19,46.69 13.68,46.18 13.68,42.8 14.42,42.07 14.42,37.88 13.66,37.11 13.66,33.89 15.31,32.24 15.31,27.77 15.06,27.51 11.7,27.51 10.91,26.72 10.91,26.25 v1(11.27,25.89)
EMMC_SMC_CLK_R: length 1.4
  TOP w0.104: v1(8.74,28.49) 8.45,28.2 RT38.2
  BOTTOM w0.112: v1(8.74,28.49) 8.48,28.74 UB4.P6
EMMC_SMC_CMD: length 82.7
  TOP w0.104: RB34.1 11.18,27.25 11.14,27.28 v1(10.71,27.28) 10.71,27 10.6,26.89 RT40.1 9.79,26.55 RT140.2
  TOP w0.127: UT7.AF26 v1(37.99,28.79)
  L3-SIG w0.076: v1(10.71,27.28) 11.32,27.89 11.96,27.89 12.64,28.57 12.64,42.27 12.56,42.35 11.32,42.35 11.25,42.42 11.25,42.57 11.32,42.65 12.56,42.65 12.64,42.73 12.64,42.88 12.56,42.96 11.32,42.96 11.25,43.03 11.25,43.18 11.32,43.26 12.56,43.26 12.64,43.34 12.64,45.01 14.23,46.6 14.96,46.6 15.67,47.3 43.63,47.3 44.24,46.69 44.24,43.62 45.08,42.78 45.08,35.18 43.83,33.94 40.91,33.94 39.26,32.29 39.26,30.69 39.25,30.68 39.25,30.05 v1(37.99,28.79)
EMMC_SMC_CMD_CONN: length 80.7
  TOP w0.104: v1(11.27,26.45) 11.03,26.45 RT140.1 ; JT1.14 v1(67.53,49.28)
  L8-SIG w0.076: v1(11.27,26.45) 12.06,27.23 15.28,27.23 15.54,27.49 15.54,32.31 14.88,32.97 14.88,45.98 16.38,47.48 44.59,47.48 45.35,46.72 64.97,46.72 v1(67.53,49.28)
EMMC_SMC_CMD_R: length 1.5
  TOP w0.104: RT40.2 10.13,28.33 v1(9.98,28.47)
  BOTTOM w0.127: UB4.P5 v1(9.98,28.47)
EMMC_SMC_DAT0: length 79.4
  TOP w0.104: RT16.1 12.54,35.54 12.84,35.83 13.46,35.83 RT139.2 13.61,35.71 RB25.1 13.61,36.37 13.72,36.48 13.87,36.48 14.12,36.72 v1(14.12,36.84)
  TOP w0.127: UT7.AE26 v1(37.2,28.78)
  L3-SIG w0.076: v1(14.12,36.84) 14.42,37.14 14.42,37.38 14.34,37.45 13.61,37.45 13.53,37.53 13.53,37.68 13.61,37.76 14.34,37.76 14.42,37.83 14.42,37.99 14.34,38.06 13.61,38.06 13.53,38.14 13.53,38.29 13.61,38.37 14.34,38.37 14.42,38.44 14.42,38.6 14.34,38.67 13.61,38.67 13.53,38.75 13.53,38.9 13.61,38.98 14.34,38.98 14.42,39.05 14.42,39.65 14.27,39.81 13.79,39.81 13.58,40.01 13.58,41.5 13.66,41.58 14.37,41.58 14.45,41.65 14.45,41.81 14.37,41.88 13.66,41.88 13.58,41.96 13.58,42.11 13.66,42.19 14.37,42.19 14.45,42.26 14.45,42.42 14.37,42.49 13.66,42.49 13.58,42.57 13.58,42.72 13.66,42.8 14.37,42.8 14.45,42.87 14.45,43.03 14.37,43.1 13.66,43.1 13.58,43.18 13.58,43.33 13.66,43.41 14.37,43.41 14.45,43.48 14.45,43.64 14.37,43.71 13.66,43.71 13.58,43.79 13.58,44.58 16.06,47.06 43.48,47.06 43.99,46.55 43.99,43.49 44.77,42.7 44.77,35.79 43.73,34.75 40.05,34.75 37.56,32.26 37.56,29.14 v1(37.2,28.78)
